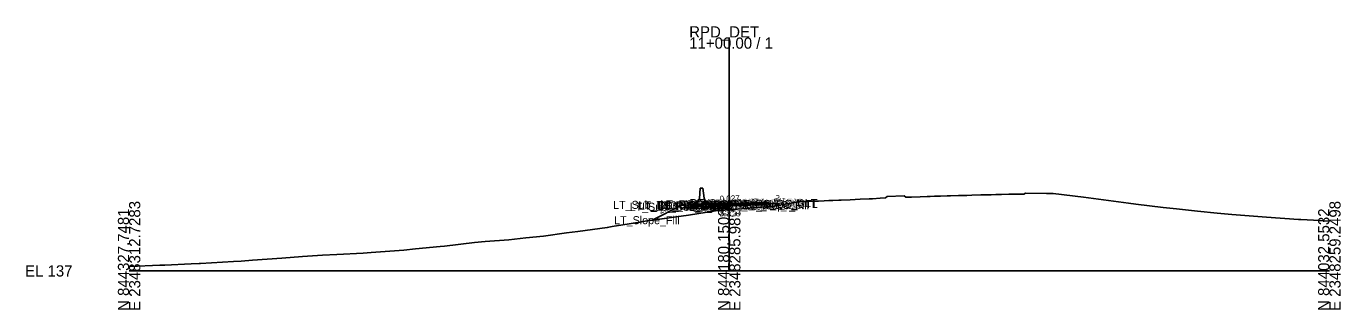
# Model space of a CAD drawing. Extents: x -26 to 2348503, y -10 to 844218.
# Drawn here: x -25.7 to 302.8, y 990.3 to 1061.1 of the extents above; entities that cross this region are included whole.
import ezdxf

# ---------------------------------------------------------------- set-up
doc = ezdxf.new("R2010")
doc.units = 0
for name, color, linetype in [('Default', 7, 'Continuous'), ('Exist Cross Section Cell', 7, 'Continuous'), ('Exist XS Center Line Elevation Label', 7, 'Continuous'), ('Exist XS Ground Line', 7, 'Continuous'), ('Old_Level_1', 7, 'Continuous'), ('Prop CMT Pvmt Course 1', 7, 'Continuous'), ('Prop CMT Pvmt Course 2', 7, 'Continuous'), ('Prop CMT Pvmt Course 3', 7, 'Continuous'), ('Prop CMT Pvmt Surface', 7, 'Continuous'), ('Prop CMT Pvmt Surface Shoulder', 7, 'Continuous'), ('Prop CMT Shld Paved Course 1', 7, 'Continuous'), ('Prop CMT Shld Paved Course 2', 7, 'Continuous'), ('Prop CMT Shld Paved Course 3', 7, 'Continuous'), ('Prop CMT Slope Grass', 7, 'Continuous'), ('Prop CMT Subgrade Earthwork', 7, 'Continuous'), ('Prop XS Earthwork Shape', 7, 'Continuous'), ('Prop XS SE Text', 7, 'Continuous'), ('Typical Median Barrier CELL', 7, 'Continuous')]:
    doc.layers.add(name, color=color, linetype=linetype)

# ---------------------------------------------------------------- blocks, each defined once
blk = doc.blocks.new('TYPE T DOUBLE FACE BARRIER')
at = {"layer": 'Typical Median Barrier CELL'}
for p, q in [((-0.33, 3.83), (-0.6, 1.3)), ((0, 3.83), (-0.33, 3.83)), ((0, 3.83), (0.33, 3.83)), ((0.33, 3.83), (0.6, 1.3)), ((-0.75, 0.91), (-1.21, 0.25)), ((-1.21, -0.17), (-1.21, 0.25)), ((0, 0), (0, 0)), ((0.75, 0.91), (1.21, 0.25)), ((1.21, -0.17), (1.21, 0.25)), ((-1.21, -0.17), (1.21, -0.17))]:
    blk.add_line(p, q, dxfattribs=at)
for centre, start, end in [((-1.43, 1.38), 325.0039, 353.9447), ((1.43, 1.38), 186.0553, 214.9937)]:
    blk.add_arc(centre, 0.833, start, end, dxfattribs=at)

msp = doc.modelspace()

# ---------------------------------------------------------------- linework, layer by layer
at = {"layer": 'Exist Cross Section Cell'}
for p, q in [((150, 1000), (150, 1058.33)), ((0, 1000), (150, 1000)), ((150, 1000), (300, 1000))]:
    msp.add_line(p, q, dxfattribs=at)
at = {"layer": 'Exist XS Ground Line'}
msp.add_lwpolyline([(0, 1001.07), (0.31, 1001.08), (7.72, 1001.41), (8.91, 1001.46), (15.5, 1001.78), (17.52, 1001.87), (17.88, 1001.89), (26.12, 1002.34), (28.04, 1002.41), (30.82, 1002.66), (38.21, 1003.21), (43.33, 1003.58), (48.37, 1003.92), (51.93, 1004.07), (58.53, 1004.41), (60.54, 1004.57), (68.7, 1005.22), (71.6, 1005.51), (77.75, 1006.14), (78.86, 1006.22), (86.35, 1007.06), (89.02, 1007.38), (94.95, 1007.75), (99.19, 1008.24), (103.56, 1008.72), (109.35, 1009.5), (112.16, 1009.87), (119.51, 1010.84), (120.77, 1011.06), (127.7, 1012.22), (129.37, 1012.5), (129.67, 1012.54), (137.98, 1013.64), (139.84, 1013.95), (146.58, 1014.99), (150.05, 1015.29), (161.22, 1016.16), (163.91, 1016.66), (167.3, 1017.27), (168.43, 1017.32), (169.63, 1017.36), (170.3, 1017.4), (172.32, 1017.47), (173.7, 1017.51), (174.86, 1017.56), (175.89, 1017.6), (177.41, 1017.67), (178.02, 1017.7), (180.2, 1017.8), (181.51, 1017.86), (182.75, 1017.91), (185.02, 1018.01), (185.81, 1018.05), (187.7, 1018.15), (189.06, 1018.24), (189.46, 1018.62), (193.71, 1018.74), (194.15, 1018.43), (195.28, 1018.46), (195.6, 1018.47), (197.69, 1018.52), (199.51, 1018.58), (200.25, 1018.61), (201.33, 1018.65), (202.81, 1018.7), (204.47, 1018.74), (205.35, 1018.77), (207.28, 1018.81), (208.02, 1018.83), (209.39, 1018.86), (210.61, 1018.9), (212.91, 1018.97), (214.52, 1019.02), (215.47, 1019.04), (216.67, 1019.06), (218.02, 1019.09), (219.91, 1019.14), (220.54, 1019.15), (223.05, 1019.19), (223.61, 1019.2), (224.09, 1019.44), (229.27, 1019.38), (231, 1019.37), (238.51, 1018.42), (249.83, 1016.95), (251.63, 1016.71), (258.44, 1015.86), (261.79, 1015.51), (267.04, 1014.95), (271.96, 1014.43), (275.64, 1014.09), (282.12, 1013.58), (284.25, 1013.42), (292.28, 1012.86), (292.85, 1012.83), (296, 1012.67), (300, 1012.46)], dxfattribs=at)
at = {"layer": 'Prop CMT Pvmt Course 1'}
for p, q in [((150, 1016.85), (142, 1016.64)), ((142, 1016.64), (142, 1016.39)), ((142, 1016.39), (150, 1016.6)), ((150, 1016.85), (158, 1017.07)), ((150, 1016.6), (150, 1016.85)), ((150, 1016.6), (150, 1016.85)), ((158, 1016.82), (150, 1016.6)), ((150, 1016.6), (150, 1016.73)), ((150, 1016.73), (150, 1016.73)), ((150, 1016.73), (150, 1016.6)), ((150, 1016.6), (150, 1016.73)), ((150, 1016.73), (150, 1016.73)), ((150, 1016.73), (150, 1016.6)), ((150, 1016.6), (150, 1016.6)), ((150, 1016.6), (150, 1016.6)), ((158, 1017.07), (158, 1016.82))]:
    msp.add_line(p, q, dxfattribs=at)
at = {"layer": 'Prop CMT Pvmt Course 2'}
for p, q in [((142, 1016.39), (150, 1016.6)), ((150, 1016.6), (142, 1016.39)), ((142, 1016.39), (142, 1016.39)), ((158, 1016.82), (150, 1016.6)), ((150, 1016.6), (158, 1016.82)), ((150, 1016.6), (150, 1016.6)), ((150, 1016.6), (150, 1016.6)), ((158, 1016.82), (158, 1016.82))]:
    msp.add_line(p, q, dxfattribs=at)
at = {"layer": 'Prop CMT Pvmt Course 3'}
for p, q in [((150, 1016.6), (142, 1016.39)), ((142, 1016.39), (142, 1016.05)), ((142, 1016.05), (150, 1016.27)), ((150, 1016.6), (158, 1016.82)), ((150, 1016.27), (150, 1016.6)), ((150, 1016.27), (150, 1016.6)), ((158, 1016.49), (150, 1016.27)), ((158, 1016.82), (158, 1016.49))]:
    msp.add_line(p, q, dxfattribs=at)
at = {"layer": 'Prop CMT Pvmt Surface'}
for q in [(142, 1016.64), (158, 1017.07)]:
    msp.add_line((150, 1016.85), q, dxfattribs=at)
at = {"layer": 'Prop CMT Pvmt Surface Shoulder'}
for p, q in [((142, 1016.64), (142, 1016.64)), ((158, 1017.07), (158, 1017.07))]:
    msp.add_line(p, q, dxfattribs=at)
at = {"layer": 'Prop CMT Shld Paved Course 1'}
for p, q in [((142, 1016.64), (141.74, 1016.38)), ((141.74, 1016.38), (142, 1016.39)), ((142, 1016.64), (142, 1016.64)), ((142, 1016.39), (142, 1016.64)), ((158, 1017.07), (158, 1017.07)), ((158, 1017.07), (158.26, 1016.82)), ((158, 1016.82), (158, 1017.07)), ((158.26, 1016.82), (158, 1016.82))]:
    msp.add_line(p, q, dxfattribs=at)
at = {"layer": 'Prop CMT Shld Paved Course 2'}
for p, q in [((142, 1016.39), (141.74, 1016.38)), ((141.74, 1016.38), (142, 1016.39)), ((141.74, 1016.38), (141.74, 1016.38)), ((142, 1016.39), (142, 1016.39)), ((158, 1016.82), (158.26, 1016.82)), ((158.26, 1016.82), (158, 1016.82)), ((158, 1016.82), (158, 1016.82)), ((158.26, 1016.82), (158.26, 1016.82))]:
    msp.add_line(p, q, dxfattribs=at)
at = {"layer": 'Prop CMT Shld Paved Course 3'}
for p, q in [((141.24, 1016.37), (140.9, 1016.03)), ((140.9, 1016.03), (142, 1016.05)), ((141.74, 1016.38), (141.24, 1016.37)), ((142, 1016.39), (141.74, 1016.38)), ((142, 1016.05), (142, 1016.39)), ((158, 1016.82), (158.26, 1016.82)), ((158, 1016.49), (158, 1016.82)), ((159.1, 1016.47), (158, 1016.49)), ((158.26, 1016.82), (158.76, 1016.81)), ((158.76, 1016.81), (159.1, 1016.47))]:
    msp.add_line(p, q, dxfattribs=at)
at = {"layer": 'Prop CMT Slope Grass'}
for p, q in [((138, 1016.32), (130.73, 1012.68)), ((142, 1016.64), (138, 1016.32)), ((158, 1017.07), (162, 1016.75)), ((162, 1016.75), (162.66, 1016.42))]:
    msp.add_line(p, q, dxfattribs=at)
at = {"layer": 'Prop CMT Subgrade Earthwork'}
for p, q in [((140.9, 1016.03), (140.43, 1016.51)), ((142, 1016.05), (140.9, 1016.03)), ((150, 1016.27), (142, 1016.05)), ((150, 1016.27), (158, 1016.49)), ((158, 1016.49), (159.1, 1016.47)), ((159.1, 1016.47), (159.57, 1016.95))]:
    msp.add_line(p, q, dxfattribs=at)
at = {"layer": 'Prop XS Earthwork Shape'}
msp.add_lwpolyline([(140.43, 1016.51), (138, 1016.32), (130.73, 1012.68), (137.98, 1013.64), (139.84, 1013.95), (146.58, 1014.99), (150.05, 1015.29), (161.22, 1016.16), (162.66, 1016.42), (162, 1016.75), (159.57, 1016.95), (159.1, 1016.47), (158, 1016.49), (150, 1016.27), (142, 1016.05), (140.9, 1016.03)], close=True, dxfattribs=at)

# ---------------------------------------------------------------- block references
at = {"layer": 'Old_Level_1', "yscale": -0.9999999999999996, "rotation": -178.51324702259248}
msp.add_blockref('TYPE T DOUBLE FACE BARRIER', (143.2, 1016.83), dxfattribs=at)

# ---------------------------------------------------------------- texts
at = {"layer": 'Default'}
for s, height, p in [('LT_Sub_Trench_Out_DLT', 2, (120.99, 1015.51)), ('LT_Sub_Trench_Out', 2, (125.11, 1015.03)), ('LT_PS3_Shelf_Out', 2, (127.23, 1015.37)), ('LT_GS_OS_CTL', 2, (127.37, 1015.32)), ('LT_PS3_OEOP', 2, (131.98, 1015.38)), ('LT_PS2_OEOP', 2, (131.98, 1015.38)), ('LT_Sub_OEOT', 2, (132.08, 1015.05)), ('LT_PV3_OEOT', 2, (132.17, 1015.39)), ('LT_PV2_OEOT', 2, (132.17, 1015.39)), ('LT_PV1_OEOT', 2, (132.74, 1015.64)), ('LT_PS1_OEOP', 2, (132.8, 1015.64)), ('RT_Sub_OEEOP', 2, (139.17, 1015.27)), ('LT_Sub_OEEOP', 2, (139.21, 1015.27)), ('RT_PV2_OEEOP', 2, (139.26, 1015.6)), ('RT_PV3_OEEOP', 2, (139.26, 1015.6)), ('LT_PV2_OEEOP', 2, (139.31, 1015.6)), ('LT_PV3_OEEOP', 2, (139.31, 1015.6)), ('RT_PV1_OEEOP', 2, (139.83, 1015.73)), ('LT_PV1_OEEOP', 2, (139.87, 1015.73)), ('RT_PV2_IEEOP', 2, (139.91, 1015.6)), ('LT_PV2_IEEOP', 2, (139.95, 1015.6)), ('RT_Sub_Trench_Out_DLT', 2, (140.09, 1015.95)), ('RT_PV1_IEEOP', 2, (140.47, 1015.73)), ('LT_PV1_IEEOP', 2, (140.52, 1015.73)), ('RT_Sub_Trench_Out', 2, (143.25, 1015.47)), ('PV2_PGL', 2, (143.91, 1015.6)), ('PV1_PGL', 2, (144.47, 1015.85)), ('RT_PS3_Shelf_Out', 2, (144.69, 1015.81)), ('RT_Sub_OEOT', 2, (148.03, 1015.49)), ('RT_PV3_OEOT', 2, (148.13, 1015.82)), ('RT_PV2_OEOT', 2, (148.13, 1015.82)), ('RT_PS3_OEOP', 2, (148.44, 1015.82)), ('RT_PS2_OEOP', 2, (148.44, 1015.82)), ('RT_PV1_OEOT', 2, (148.69, 1016.07)), ('RT_PS1_OEOP', 2, (148.76, 1016.07)), ('RT_GS_OS_CTL', 2, (151.32, 1015.75)), ('RT_Slope_Fill', 2, (153.13, 1015.42)), ('LT_Slope_Fill', 2, (121.25, 1011.68)), ('-', 0.0001, (0, 1000))]:
    msp.add_text(s, height=height, dxfattribs=at).set_placement(p)
at = {"layer": 'Exist Cross Section Cell'}
for s, p in [('11+00.00 / 1', (140, 1055.53)), ('RPD_DET', (140, 1058.33)), ('EL 137', (-26, 998.6))]:
    msp.add_text(s, height=2.8, dxfattribs=at).set_placement(p)
for s, p in [('N 844327.7481', (0, 990)), ('E 2348312.7283', (2.8, 990)), ('N 844180.1506', (150, 990)), ('E 2348285.9890', (152.8, 990)), ('N 844032.5532', (300, 990)), ('E 2348259.2498', (302.8, 990))]:
    msp.add_text(s, height=2.8, rotation=90, dxfattribs=at).set_placement(p)
at = {"layer": 'Exist XS Center Line Elevation Label'}
msp.add_text('152.28', height=1.2, dxfattribs=at).set_placement((147.55, 1013.68))
at = {"layer": 'Prop XS SE Text'}
for s, rotation, p in [('0.027', 1.5581, (147.62, 1017.29)), ('2:1', 333.4349, (161.12, 1017.82)), ('2:1', 26.5651, (132.81, 1014.21))]:
    msp.add_text(s, height=1.5, rotation=rotation, dxfattribs=at).set_placement(p)

doc.saveas('drawing.dxf')
